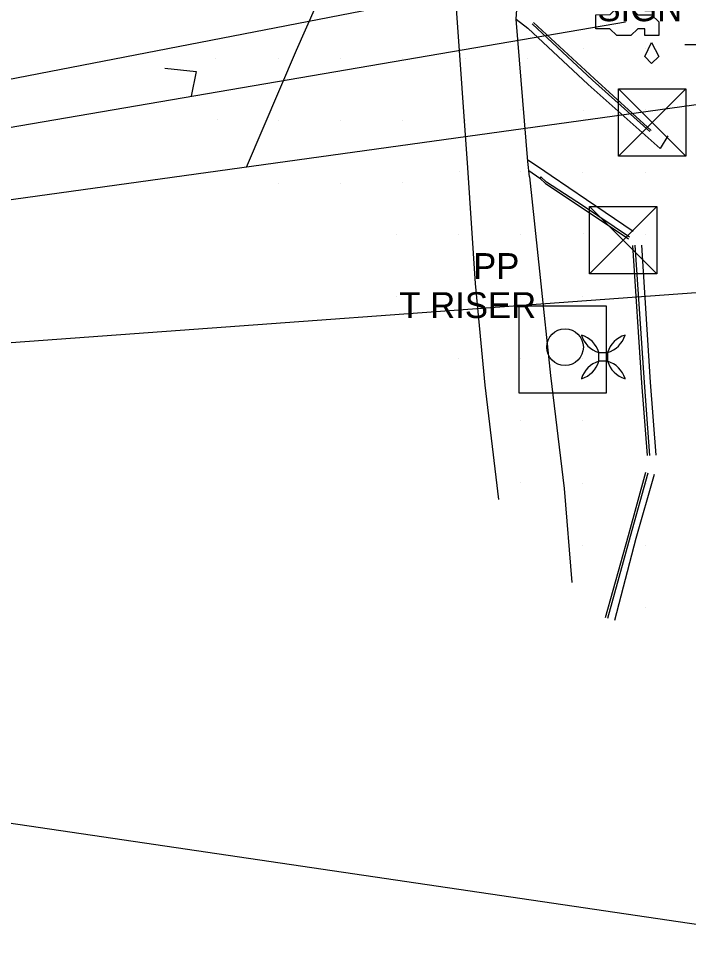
# Model space of a CAD drawing. Extents: x 1602514 to 1609837, y 863887 to 871157.
# Drawn here: x 1604592.6 to 1604754.1, y 866343.2 to 866566.1 of the extents above; entities that cross this region are included whole.
import ezdxf

# ---------------------------------------------------------------- set-up
doc = ezdxf.new("R2010")
doc.units = 0
for name, color, linetype in [('Photo-Anchor', 7, 'Continuous'), ('Property-Fences', 7, 'Continuous'), ('Roadway-Signs', 7, 'Continuous'), ('Survey-Curbs', 7, 'Continuous'), ('Survey-Edge of pavement', 7, 'Continuous'), ('Survey-Spot dirt', 7, 'Continuous'), ('Text General Notes', 7, 'Continuous'), ('Utility-Pole', 7, 'Continuous'), ('Utility-Telephone', 7, 'Continuous'), ('Utility-Water', 7, 'Continuous')]:
    doc.layers.add(name, color=color, linetype=linetype)

msp = doc.modelspace()

# ---------------------------------------------------------------- linework, layer by layer
at = {"layer": 'Photo-Anchor'}
msp.add_lwpolyline([(1604732.5, 866485.51), (1604734.6, 866485.51), (1604734.6, 866483.41), (1604732.5, 866483.41)], close=True, dxfattribs=at)
msp.add_lwpolyline([(1604732.5, 866485.51), (1604734.6, 866485.51), (1604734.6, 866483.41), (1604732.5, 866483.41)], close=True, dxfattribs=at)
for centre, radius, start, end in [((1604726.5, 866483.7), 6.27, 16.7236, 73.2821), ((1604734.32, 866491.53), 6.29, 196.8106, 253.1951), ((1604726.5, 866483.7), 6.27, 16.7236, 73.2821), ((1604734.32, 866491.53), 6.29, 196.8106, 253.1951), ((1604740.6, 866483.7), 6.27, 106.7179, 163.2764), ((1604732.78, 866491.53), 6.29, 286.8049, 343.1894), ((1604740.6, 866483.7), 6.27, 106.7179, 163.2764), ((1604732.78, 866491.53), 6.29, 286.8049, 343.1894), ((1604726.5, 866485.21), 6.27, 286.7179, 343.2764), ((1604734.32, 866477.39), 6.29, 106.8049, 163.1894), ((1604726.5, 866485.21), 6.27, 286.7179, 343.2764), ((1604734.32, 866477.39), 6.29, 106.8049, 163.1894), ((1604740.6, 866485.21), 6.27, 196.7236, 253.2821), ((1604732.78, 866477.39), 6.29, 16.8106, 73.1951), ((1604740.6, 866485.21), 6.27, 196.7236, 253.2821), ((1604732.78, 866477.39), 6.29, 16.8106, 73.1951)]:
    msp.add_arc(centre, radius, start, end, dxfattribs=at)
at = {"layer": 'Property-Fences'}
for p, q in [((1604737.19, 866532.83), (1604753.44, 866549.08)), ((1604753.44, 866532.83), (1604737.19, 866549.08)), ((1604737.19, 866549.08), (1604753.44, 866549.08)), ((1604737.19, 866532.83), (1604737.19, 866549.08)), ((1604737.19, 866532.83), (1604753.44, 866549.08)), ((1604753.44, 866532.83), (1604737.19, 866549.08)), ((1604737.19, 866549.08), (1604753.44, 866549.08)), ((1604737.19, 866532.83), (1604737.19, 866549.08)), ((1604753.44, 866549.08), (1604753.44, 866532.83)), ((1604753.44, 866549.08), (1604753.44, 866532.83)), ((1604753.44, 866532.83), (1604737.19, 866532.83)), ((1604753.44, 866532.83), (1604737.19, 866532.83)), ((1604730.23, 866504.45), (1604746.48, 866520.7)), ((1604746.48, 866504.45), (1604730.23, 866520.7)), ((1604730.23, 866520.7), (1604746.48, 866520.7)), ((1604730.23, 866504.45), (1604730.23, 866520.7)), ((1604730.23, 866504.45), (1604746.48, 866520.7)), ((1604746.48, 866504.45), (1604730.23, 866520.7)), ((1604730.23, 866520.7), (1604746.48, 866520.7)), ((1604730.23, 866504.45), (1604730.23, 866520.7)), ((1604746.48, 866520.7), (1604746.48, 866504.45)), ((1604746.48, 866520.7), (1604746.48, 866504.45)), ((1604746.48, 866504.45), (1604730.23, 866504.45)), ((1604746.48, 866504.45), (1604730.23, 866504.45))]:
    msp.add_line(p, q, dxfattribs=at)
at = {"layer": 'Roadway-Signs'}
msp.add_line((1604753.24, 866559.75), (1604774.14, 866559.75), dxfattribs=at)
msp.add_line((1604753.24, 866559.75), (1604774.14, 866559.75), dxfattribs=at)
at = {"layer": 'Survey-Curbs'}
for points in [[(1604716.44, 866564.74), (1604730.97, 866551.2), (1604744.78, 866538.79)], [(1604716.44, 866564.74), (1604730.97, 866551.2), (1604744.78, 866538.79)], [(1604716.78, 866565.07), (1604731.37, 866551.59), (1604745.11, 866539.07)], [(1604716.78, 866565.07), (1604731.37, 866551.59), (1604745.11, 866539.07)], [(1604715.63, 866529.38), (1604718.3, 866527.52), (1604719.64, 866526.25), (1604728.27, 866520.54), (1604739.62, 866512.9)], [(1604715.63, 866529.38), (1604718.3, 866527.52), (1604719.64, 866526.25), (1604728.27, 866520.54), (1604739.62, 866512.9)], [(1604739.9, 866513.35), (1604728.54, 866520.94), (1604719.86, 866526.56), (1604718.55, 866527.89), (1604718.3, 866527.52)], [(1604739.9, 866513.35), (1604728.54, 866520.94), (1604719.86, 866526.56), (1604718.55, 866527.89), (1604718.3, 866527.52)], [(1604744.2, 866460.64), (1604742.89, 866478.24), (1604740.69, 866511.35)], [(1604744.2, 866460.64), (1604742.89, 866478.24), (1604740.69, 866511.35)], [(1604744.78, 866460.66), (1604743.47, 866478.28), (1604741.23, 866511.36)], [(1604744.78, 866460.66), (1604743.47, 866478.28), (1604741.23, 866511.36)], [(1604734.07, 866421.58), (1604739.66, 866441.36), (1604743.81, 866456.68)], [(1604734.07, 866421.58), (1604739.66, 866441.36), (1604743.81, 866456.68)], [(1604734.64, 866421.42), (1604740.12, 866441.21), (1604744.38, 866456.54)], [(1604734.64, 866421.42), (1604740.12, 866441.21), (1604744.38, 866456.54)]]:
    msp.add_lwpolyline(points, dxfattribs=at)
at = {"layer": 'Survey-Edge of pavement'}
msp.add_line((1604749.14, 866537.78), (1604747.27, 866534.68), dxfattribs=at)
msp.add_line((1604749.14, 866537.78), (1604747.27, 866534.68), dxfattribs=at)
for points in [[(1604686.79, 866682.57), (1604689.3, 866661.29), (1604689.69, 866649.24), (1604691.23, 866624.21), (1604698.13, 866568.43), (1604700.86, 866530.06)], [(1604686.79, 866682.57), (1604689.3, 866661.29), (1604689.69, 866649.24), (1604691.23, 866624.21), (1604698.13, 866568.43), (1604700.86, 866530.06)], [(1604715.81, 866527.88), (1604715.36, 866531.59), (1604712.53, 866565.89), (1604712.79, 866569.37), (1604706.85, 866624.62), (1604704.08, 866662.62), (1604703.57, 866678.57)], [(1604715.81, 866527.88), (1604715.36, 866531.59), (1604712.53, 866565.89), (1604712.79, 866569.37), (1604706.85, 866624.62), (1604704.08, 866662.62), (1604703.57, 866678.57)], [(1604647.61, 866530.22), (1604659.59, 866558.42), (1604671.43, 866585.21), (1604680.14, 866603.95), (1604687.52, 866616.91), (1604691.23, 866624.21)], [(1604647.61, 866530.22), (1604659.59, 866558.42), (1604671.43, 866585.21), (1604680.14, 866603.95), (1604687.52, 866616.91), (1604691.23, 866624.21)], [(1604712.53, 866565.89), (1604715.37, 866563.71), (1604729.91, 866550.17), (1604743.63, 866537.92), (1604747.27, 866534.68)], [(1604712.53, 866565.89), (1604715.37, 866563.71), (1604729.91, 866550.17), (1604743.63, 866537.92), (1604747.27, 866534.68)], [(1604627.92, 866554.07), (1604635.44, 866553.26), (1604634.2, 866547.31)], [(1604627.92, 866554.07), (1604635.44, 866553.26), (1604634.2, 866547.31)], [(1604740.75, 866514.73), (1604729.49, 866522.34), (1604720.97, 866528.08), (1604719.44, 866529.18), (1604715.33, 866532.01)], [(1604740.75, 866514.73), (1604729.49, 866522.34), (1604720.97, 866528.08), (1604719.44, 866529.18), (1604715.33, 866532.01)], [(1604700.86, 866530.06), (1604702.72, 866502.15), (1604705.03, 866477.66), (1604708.32, 866450.04)], [(1604700.86, 866530.06), (1604702.72, 866502.15), (1604705.03, 866477.66), (1604708.32, 866450.04)], [(1604715.81, 866527.88), (1604718.32, 866503.63), (1604720.87, 866479.95), (1604724.14, 866452.74), (1604726.02, 866430.06)], [(1604715.81, 866527.88), (1604718.32, 866503.63), (1604720.87, 866479.95), (1604724.14, 866452.74), (1604726.02, 866430.06)], [(1604746.3, 866460.77), (1604744.95, 866478.37), (1604742.84, 866511.38)], [(1604746.3, 866460.77), (1604744.95, 866478.37), (1604742.84, 866511.38)], [(1604736.32, 866420.97), (1604741.47, 866440.78), (1604745.87, 866456.18)], [(1604736.32, 866420.97), (1604741.47, 866440.78), (1604745.87, 866456.18)]]:
    msp.add_lwpolyline(points, dxfattribs=at)
at = {"layer": 'Survey-Spot dirt'}
for p, q in [((1604728.71, 866558.82), (1604728.71, 866558.82)), ((1604728.71, 866558.82), (1604728.71, 866558.82)), ((1604743.69, 866558.89), (1604743.69, 866558.89)), ((1604743.69, 866558.89), (1604743.69, 866558.89)), ((1604640.2, 866556.37), (1604640.2, 866556.37)), ((1604640.2, 866556.37), (1604640.2, 866556.37)), ((1604655.2, 866556.41), (1604655.2, 866556.41)), ((1604655.2, 866556.41), (1604655.2, 866556.41)), ((1604670.22, 866556.48), (1604670.22, 866556.48)), ((1604670.22, 866556.48), (1604670.22, 866556.48)), ((1604685.22, 866556.41), (1604685.22, 866556.41)), ((1604685.22, 866556.41), (1604685.22, 866556.41)), ((1604700.25, 866556.38), (1604700.25, 866556.38)), ((1604700.25, 866556.38), (1604700.25, 866556.38)), ((1604715.24, 866556.35), (1604715.24, 866556.35)), ((1604715.24, 866556.35), (1604715.24, 866556.35)), ((1604713.62, 866544.05), (1604713.62, 866544.05)), ((1604713.62, 866544.05), (1604713.62, 866544.05)), ((1604728.73, 866543.93), (1604728.73, 866543.93)), ((1604728.73, 866543.93), (1604728.73, 866543.93)), ((1604743.65, 866544.03), (1604743.65, 866544.03)), ((1604743.65, 866544.03), (1604743.65, 866544.03)), ((1604640.5, 866541.66), (1604640.5, 866541.66)), ((1604640.5, 866541.66), (1604640.5, 866541.66)), ((1604655.19, 866541.4), (1604655.19, 866541.4)), ((1604655.19, 866541.4), (1604655.19, 866541.4)), ((1604670.23, 866541.44), (1604670.23, 866541.44)), ((1604670.23, 866541.44), (1604670.23, 866541.44)), ((1604685.26, 866541.41), (1604685.26, 866541.41)), ((1604685.26, 866541.41), (1604685.26, 866541.41)), ((1604700.34, 866541.37), (1604700.34, 866541.37)), ((1604700.34, 866541.37), (1604700.34, 866541.37)), ((1604698.86, 866529.07), (1604698.86, 866529.07)), ((1604698.86, 866529.07), (1604698.86, 866529.07)), ((1604713.65, 866529.07), (1604713.65, 866529.07)), ((1604713.65, 866529.07), (1604713.65, 866529.07)), ((1604728.63, 866528.91), (1604728.63, 866528.91)), ((1604728.63, 866528.91), (1604728.63, 866528.91)), ((1604743.68, 866528.98), (1604743.68, 866528.98)), ((1604743.68, 866528.98), (1604743.68, 866528.98)), ((1604655.21, 866526.38), (1604655.21, 866526.38)), ((1604655.21, 866526.38), (1604655.21, 866526.38)), ((1604670.16, 866526.34), (1604670.16, 866526.34)), ((1604670.16, 866526.34), (1604670.16, 866526.34)), ((1604685.21, 866526.44), (1604685.21, 866526.44)), ((1604685.21, 866526.44), (1604685.21, 866526.44)), ((1604683.61, 866513.86), (1604683.61, 866513.86)), ((1604683.61, 866513.86), (1604683.61, 866513.86)), ((1604698.74, 866513.96), (1604698.74, 866513.96)), ((1604698.74, 866513.96), (1604698.74, 866513.96)), ((1604713.6, 866513.92), (1604713.6, 866513.92)), ((1604713.6, 866513.92), (1604713.6, 866513.92)), ((1604728.87, 866514.1), (1604728.87, 866514.1)), ((1604728.87, 866514.1), (1604728.87, 866514.1)), ((1604743.67, 866513.93), (1604743.67, 866513.93)), ((1604743.67, 866513.93), (1604743.67, 866513.93)), ((1604683.67, 866498.96), (1604683.67, 866498.96)), ((1604683.67, 866498.96), (1604683.67, 866498.96)), ((1604698.66, 866498.95), (1604698.66, 866498.95)), ((1604698.66, 866498.95), (1604698.66, 866498.95)), ((1604713.6, 866498.9), (1604713.6, 866498.9)), ((1604713.6, 866498.9), (1604713.6, 866498.9)), ((1604728.67, 866499.03), (1604728.67, 866499.03)), ((1604728.67, 866499.03), (1604728.67, 866499.03)), ((1604743.59, 866498.97), (1604743.59, 866498.97)), ((1604743.59, 866498.97), (1604743.59, 866498.97)), ((1604698.66, 866483.96), (1604698.66, 866483.96)), ((1604698.66, 866483.96), (1604698.66, 866483.96)), ((1604713.59, 866483.96), (1604713.59, 866483.96)), ((1604713.59, 866483.96), (1604713.59, 866483.96)), ((1604728.67, 866484.04), (1604728.67, 866484.04)), ((1604728.67, 866484.04), (1604728.67, 866484.04)), ((1604743.57, 866483.98), (1604743.57, 866483.98)), ((1604743.57, 866483.98), (1604743.57, 866483.98)), ((1604713.66, 866469.06), (1604713.66, 866469.06)), ((1604713.66, 866469.06), (1604713.66, 866469.06)), ((1604728.67, 866469.01), (1604728.67, 866469.01)), ((1604728.67, 866469.01), (1604728.67, 866469.01)), ((1604713.65, 866454.05), (1604713.65, 866454.05)), ((1604713.65, 866454.05), (1604713.65, 866454.05)), ((1604728.62, 866454.04), (1604728.62, 866454.04)), ((1604728.62, 866454.04), (1604728.62, 866454.04)), ((1604743.91, 866453.98), (1604743.91, 866453.98)), ((1604743.91, 866453.98), (1604743.91, 866453.98)), ((1604728.63, 866438.97), (1604728.63, 866438.97)), ((1604728.63, 866438.97), (1604728.63, 866438.97)), ((1604743.7, 866438.91), (1604743.7, 866438.91)), ((1604743.7, 866438.91), (1604743.7, 866438.91)), ((1604743.64, 866423.96), (1604743.64, 866423.96)), ((1604743.64, 866423.96), (1604743.64, 866423.96))]:
    msp.add_line(p, q, dxfattribs=at)
at = {"layer": 'Text General Notes'}
for p, q in [((1604738.94, 866565.21), (1604065.19, 866449.51)), ((1604738.94, 866565.21), (1604065.19, 866449.51)), ((1605088.05, 866524.09), (1604065.19, 866449.51)), ((1605088.05, 866524.09), (1604065.19, 866449.51)), ((1604065.19, 866449.51), (1605339.88, 866261.5)), ((1604065.19, 866449.51), (1605339.88, 866261.5))]:
    msp.add_line(p, q, dxfattribs=at)
msp.add_lwpolyline([(1605012.85, 866633.37), (1604065.19, 866449.51), (1605014.37, 866581.28)], dxfattribs=at)
msp.add_lwpolyline([(1605012.85, 866633.37), (1604065.19, 866449.51), (1605014.37, 866581.28)], dxfattribs=at)
at = {"layer": 'Utility-Pole'}
msp.add_lwpolyline([(1604713.25, 866496.75), (1604734.25, 866496.75), (1604734.25, 866475.75), (1604713.25, 866475.75)], close=True, dxfattribs=at)
msp.add_lwpolyline([(1604713.25, 866496.75), (1604734.25, 866496.75), (1604734.25, 866475.75), (1604713.25, 866475.75)], close=True, dxfattribs=at)
at = {"layer": 'Utility-Telephone'}
msp.add_circle((1604724.34, 866486.81), 4.42, dxfattribs=at)
msp.add_circle((1604724.34, 866486.81), 4.42, dxfattribs=at)
at = {"layer": 'Utility-Water'}
for points in [[(1604731.79, 866566.96), (1604735.2, 866567.01), (1604736.82, 866568.64), (1604740.19, 866568.64), (1604741.86, 866566.96), (1604745.22, 866566.96), (1604746.91, 866565.28), (1604746.91, 866561.92), (1604743.55, 866561.92), (1604743.55, 866563.6), (1604741.86, 866563.6), (1604740.19, 866561.92), (1604736.82, 866561.92), (1604735.15, 866563.6), (1604731.79, 866563.6)], [(1604731.79, 866566.96), (1604735.2, 866567.01), (1604736.82, 866568.64), (1604740.19, 866568.64), (1604741.86, 866566.96), (1604745.22, 866566.96), (1604746.91, 866565.28), (1604746.91, 866561.92), (1604743.55, 866561.92), (1604743.55, 866563.6), (1604741.86, 866563.6), (1604740.19, 866561.92), (1604736.82, 866561.92), (1604735.15, 866563.6), (1604731.79, 866563.6)], [(1604745.22, 866560.24), (1604746.91, 866556.88), (1604745.22, 866555.2), (1604743.55, 866556.88)], [(1604745.22, 866560.24), (1604746.91, 866556.88), (1604745.22, 866555.2), (1604743.55, 866556.88)]]:
    msp.add_lwpolyline(points, close=True, dxfattribs=at)

# ---------------------------------------------------------------- texts
at = {"layer": 'Roadway-Signs'}
msp.add_text('SIGN', height=6.25, dxfattribs=at).set_placement((1604732.16, 866565.4))
msp.add_text('SIGN', height=6.25, dxfattribs=at).set_placement((1604732.16, 866565.4))
at = {"layer": 'Utility-Pole'}
msp.add_text('PP', height=6.251, dxfattribs=at).set_placement((1604702.19, 866503.22))
msp.add_text('PP', height=6.251, dxfattribs=at).set_placement((1604702.19, 866503.22))
at = {"layer": 'Utility-Telephone'}
msp.add_text('T RISER', height=6.251, dxfattribs=at).set_placement((1604684.41, 866493.81))
msp.add_text('T RISER', height=6.251, dxfattribs=at).set_placement((1604684.41, 866493.81))

doc.saveas('drawing.dxf')
